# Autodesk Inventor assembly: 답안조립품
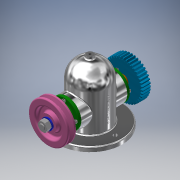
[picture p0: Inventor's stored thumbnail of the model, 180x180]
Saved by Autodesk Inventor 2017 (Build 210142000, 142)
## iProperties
Created: 2019-11
Part Number: 답안조립품
Document SubType Name: Assembly
Designer: 1-00-lg-1
Author: 1-00-lg-1
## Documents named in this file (14)
- C:\Users\1-00-lg-1\Desktop\491104V1022\답안조립품.iam
- C:\Users\1-00-lg-1\Desktop\491104V1022\본체.ipt
- C:\Users\1-00-lg-1\Desktop\491104V1022\축.ipt
- C:\Users\1-00-lg-1\Desktop\491104V1022\베어링 6203.ipt
- C:\Users\1-00-lg-1\Desktop\491104V1022\부시.ipt
- C:\Users\1-00-lg-1\Desktop\491104V1022\커버.ipt
- C:\Users\1-00-lg-1\Desktop\491104V1022\오일 실 26 38 8.ipt
- C:\Users\1-00-lg-1\Desktop\491104V1022\볼트 M4.ipt
- C:\Users\1-00-lg-1\Desktop\491104V1022\키 5x5x12.ipt
- C:\Users\1-00-lg-1\Desktop\491104V1022\V-벨트풀리.ipt
- V-벨트풀리.ipt
- C:\Users\1-00-lg-1\Desktop\491104V1022\스퍼기어.ipt
- C:\Users\1-00-lg-1\Desktop\491104V1022\와셔 12x24.ipt
- C:\Users\1-00-lg-1\Desktop\491104V1022\너트 M12x1.25.ipt
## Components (1 placed, 1 different names)
1. V-벨트풀리:1 — Mate:27, Mate:28, Mate:29, Mate:36
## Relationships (4: Mate 4)
- Mate:27: V-벨트풀리:1
- Mate:28: V-벨트풀리:1
- Mate:29: V-벨트풀리:1
- Mate:36: V-벨트풀리:1
